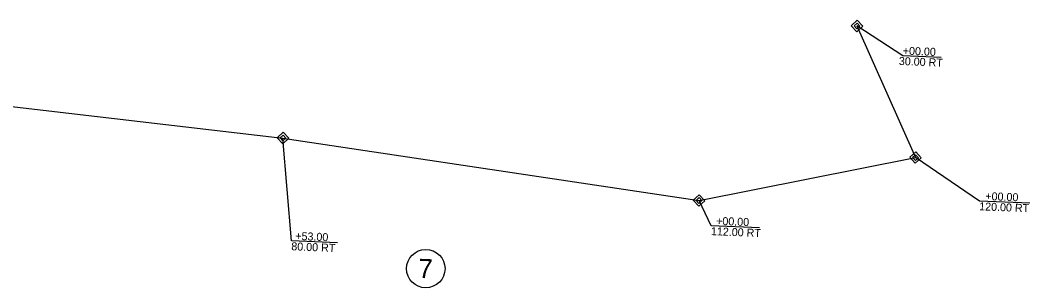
# Model space of a CAD drawing. Extents: x 1002576 to 1014655, y 551673 to 557994.
# Drawn here: x 1014025 to 1014655, y 551911 to 552079 of the extents above; entities that cross this region are included whole.
import ezdxf

# ---------------------------------------------------------------- set-up
doc = ezdxf.new("R2010")
doc.units = 0
for name, color, linetype in [('Exist Hydro Stream or Body of Water', 7, 'Continuous'), ('Exist Other Culture Area Outline', 7, 'Continuous'), ('Exist Roads EOP Other', 7, 'Continuous'), ('Exist Structure Major Deck Tunnel Box Culvert', 7, 'Continuous'), ('Exist Utilities Power Pole CELL', 7, 'Continuous')]:
    doc.layers.add(name, color=color, linetype=linetype)

msp = doc.modelspace()

# ---------------------------------------------------------------- linework, layer by layer
at = {"layer": 'Exist Hydro Stream or Body of Water'}
for p, q in [((1014547.51, 552074.95), (1014547.51, 552074.95)), ((1014188.95, 552004.91), (1014188.95, 552004.91)), ((1014584.07, 551992.71), (1014584.07, 551992.71)), ((1014448.83, 551965.86), (1014448.83, 551965.86))]:
    msp.add_line(p, q, dxfattribs=at)
at = {"layer": 'Exist Other Culture Area Outline'}
for p, q in [((1014547.51, 552074.95), (1014584.07, 551992.71)), ((1014008.03, 552025.92), (1014188.95, 552004.91)), ((1014188.95, 552004.91), (1014448.83, 551965.86)), ((1014448.83, 551965.86), (1014584.07, 551992.71))]:
    msp.add_line(p, q, dxfattribs=at)
at = {"layer": 'Exist Roads EOP Other'}
for p, q in [((1014600.18, 552055.29), (1014576.16, 552056.26)), ((1014655.46, 551964.28), (1014624.02, 551965.56)), ((1014486.69, 551948.83), (1014456.44, 551950.06)), ((1014223.03, 551939.41), (1014194.35, 551940.58))]:
    msp.add_line(p, q, dxfattribs=at)
for points in [[(1014576.16, 552056.26), (1014547.51, 552074.95)], [(1014194.35, 551940.58), (1014188.95, 552004.91)], [(1014624.02, 551965.56), (1014584.07, 551992.71)], [(1014456.44, 551950.06), (1014448.83, 551965.86)]]:
    msp.add_lwpolyline(points, dxfattribs=at)
at = {"layer": 'Exist Structure Major Deck Tunnel Box Culvert'}
for points in [[(1014551.11, 552074.81), (1014547.37, 552071.36), (1014543.92, 552075.1), (1014547.66, 552078.55)], [(1014549.31, 552074.88), (1014547.44, 552073.16), (1014545.72, 552075.03), (1014547.59, 552076.75)], [(1014192.55, 552004.76), (1014188.81, 552001.31), (1014185.36, 552005.06), (1014189.1, 552008.51)], [(1014190.75, 552004.84), (1014188.88, 552003.11), (1014187.15, 552004.98), (1014189.03, 552006.71)], [(1014587.67, 551992.57), (1014583.92, 551989.12), (1014580.47, 551992.86), (1014584.22, 551996.31)], [(1014585.87, 551992.64), (1014584, 551990.91), (1014582.27, 551992.79), (1014584.14, 551994.51)], [(1014452.42, 551965.72), (1014448.68, 551962.27), (1014445.23, 551966.01), (1014448.97, 551969.46)], [(1014450.62, 551965.79), (1014448.75, 551964.07), (1014447.03, 551965.94), (1014448.9, 551967.66)]]:
    msp.add_lwpolyline(points, close=True, dxfattribs=at)
at = {"layer": 'Exist Utilities Power Pole CELL'}
msp.add_line((1014278.17, 551923.33), (1014278.17, 551923.33), dxfattribs=at)
msp.add_circle((1014278.17, 551923.33), 12, dxfattribs=at)

# ---------------------------------------------------------------- texts
at = {"layer": 'Exist Roads EOP Other'}
for s, p in [('+00.00', (1014576.04, 552057.05)), ('30.00 RT', (1014573.57, 552050.59)), ('+00.00', (1014627.61, 551966.19)), ('120.00 RT', (1014623.76, 551959.79)), ('+00.00', (1014459.44, 551950.71)), ('+53.00', (1014196.56, 551941.27)), ('112.00 RT', (1014456.19, 551944.28)), ('80.00 RT', (1014194.09, 551934.81))]:
    msp.add_text(s, height=5, rotation=357.67072, dxfattribs=at).set_placement(p)
at = {"layer": 'Exist Utilities Power Pole CELL'}
msp.add_text('7', height=12, rotation=357.67072, dxfattribs=at).set_placement((1014273.35, 551917.52))

doc.saveas('drawing.dxf')
